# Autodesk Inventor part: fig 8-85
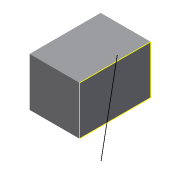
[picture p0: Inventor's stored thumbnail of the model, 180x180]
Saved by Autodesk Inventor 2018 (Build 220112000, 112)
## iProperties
Created: 2009-04
Part Number: fig 8-85
Document SubType Name: Modeling
Designer: Sham
Density: 1 g/cm^3
Material: Generic
Appearance: Default
Author: Sham
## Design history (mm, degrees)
sketch "Sketch5"
  geometry: L1 (14, -13.6)-(0, -13.6); L2 (0, -13.6)-(0, 0); L3 (0, 0)-(14, 0); L4 (14, 0)-(14, -13.6)
  constraints: 8 end point
extrude "Extrusion2" new body sketch "Sketch5" distance "d3" = 20; taper "d4" = 0 deg
sketch "Sketch7"
  geometry: L1 (13.6, 20)-(0, 20) reference; L2 (0, 0)-(0, 20) reference; L3 (13.6, 0)-(0, 0) reference; L4 (13.6, 0)-(13.6, 20) reference; L5 (-1.442, 10.604)-(21.986, 6.075)
  constraints: 2 end point
body "Solid2"
